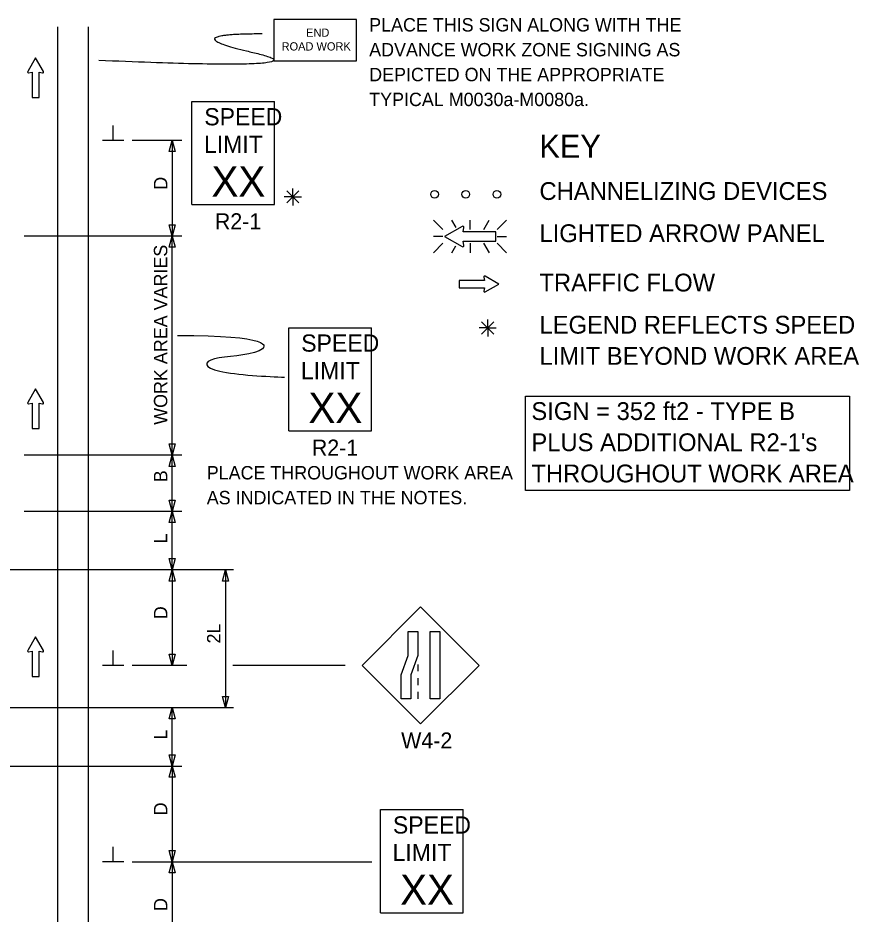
# Model space of a CAD drawing. Extents: x 16504 to 18480, y 5523 to 6928.
# Drawn here: x 16983.9 to 17424, y 6455.4 to 6923.9 of the extents above; entities that cross this region are included whole.
import ezdxf

# ---------------------------------------------------------------- set-up
doc = ezdxf.new("R2010")
doc.units = 0
for name, color, linetype in [('MT_SCRATCH_LEVEL_E', 7, 'Continuous'), ('PAVT_EDGE_EX', 7, 'Continuous'), ('TRAFFIC_SIGNS_PR', 7, 'Continuous'), ('TYPICAL_TEXT_DIMEN_EX', 7, 'Continuous'), ('TYPICAL_TEXT_DIMEN_PR', 7, 'Continuous')]:
    doc.layers.add(name, color=color, linetype=linetype)

msp = doc.modelspace()

# ---------------------------------------------------------------- linework, layer by layer
at = {"layer": 'MT_SCRATCH_LEVEL_E'}
for p, q in [((16993.16, 6903.1), (16989.05, 6895.86)), ((16997.31, 6895.86), (16993.16, 6903.1)), ((16989.53, 6895.17), (16991.31, 6895.49)), ((16991.31, 6895.49), (16991.31, 6882.23)), ((16995.05, 6882.23), (16995.05, 6895.49)), ((16995.05, 6895.49), (16996.83, 6895.17)), ((16991.31, 6882.23), (16995.05, 6882.23)), ((17227.93, 6786.61), (17214.67, 6786.61)), ((17214.67, 6786.61), (17214.67, 6782.86)), ((17227.62, 6788.38), (17227.93, 6786.61)), ((17235.54, 6784.76), (17228.3, 6788.87)), ((17228.3, 6780.61), (17235.54, 6784.76)), ((17214.67, 6782.86), (17227.93, 6782.86)), ((17227.93, 6782.86), (17227.62, 6781.09)), ((16993.16, 6730.05), (16989.05, 6722.81)), ((16997.31, 6722.81), (16993.16, 6730.05)), ((16989.53, 6722.12), (16991.31, 6722.44)), ((16991.31, 6722.44), (16991.31, 6709.18)), ((16995.05, 6709.18), (16995.05, 6722.44)), ((16995.05, 6722.44), (16996.83, 6722.12)), ((16991.31, 6709.18), (16995.05, 6709.18)), ((16993.16, 6600.4), (16989.05, 6593.16)), ((16997.31, 6593.16), (16993.16, 6600.4)), ((16989.53, 6592.48), (16991.31, 6592.79)), ((16991.31, 6592.79), (16991.31, 6579.54)), ((16995.05, 6579.54), (16995.05, 6592.79)), ((16995.05, 6592.79), (16996.83, 6592.48)), ((16991.31, 6579.54), (16995.05, 6579.54))]:
    msp.add_line(p, q, dxfattribs=at)
for centre, start, end in [((16989.46, 6895.63), 150.4248, 279.9638), ((16996.9, 6895.63), 260.0362, 29.7731), ((17228.07, 6788.46), 60.4248, 189.9638), ((17228.07, 6781.02), 170.0362, 299.7731), ((16989.46, 6722.58), 150.4248, 279.9638), ((16996.9, 6722.58), 260.0362, 29.7731), ((16989.46, 6592.94), 150.4248, 279.9638), ((16996.9, 6592.94), 260.0362, 29.7731)]:
    msp.add_arc(centre, 0.463, start, end, dxfattribs=at)
at = {"layer": 'PAVT_EDGE_EX'}
for p, q in [((17004.63, 6919.19), (17004.63, 6002.83)), ((17020.63, 6919.19), (17020.63, 6002.83))]:
    msp.add_line(p, q, dxfattribs=at)
at = {"layer": 'TRAFFIC_SIGNS_PR'}
for p, q in [((17074.95, 6880.28), (17118.15, 6880.28)), ((17074.95, 6826.28), (17074.95, 6880.28)), ((17118.15, 6826.28), (17118.15, 6880.28)), ((17074.95, 6826.28), (17118.15, 6826.28)), ((17201.35, 6818.14), (17206.28, 6813.21)), ((17213.11, 6814.32), (17210.91, 6818.14)), ((17220.43, 6813.21), (17220.43, 6818.14)), ((17227.67, 6813.21), (17230.52, 6818.14)), ((17234.58, 6813.21), (17239.52, 6818.14)), ((17206.28, 6809.65), (17201.35, 6809.65)), ((17234.58, 6809.65), (17239.52, 6809.65)), ((17201.35, 6801.16), (17206.28, 6806.09)), ((17210.86, 6801.16), (17212.97, 6804.82)), ((17220.43, 6806.09), (17220.43, 6801.16)), ((17230.56, 6801.16), (17227.71, 6806.09)), ((17234.58, 6806.09), (17239.52, 6801.16)), ((17125.67, 6761.94), (17168.87, 6761.94)), ((17125.67, 6707.94), (17125.67, 6761.94)), ((17168.87, 6707.94), (17168.87, 6761.94)), ((17125.67, 6707.94), (17168.87, 6707.94)), ((17194.59, 6615.92), (17164.04, 6585.37)), ((17225.13, 6585.37), (17194.59, 6615.92)), ((17164.04, 6585.37), (17194.59, 6554.82)), ((17193.18, 6585.92), (17193.18, 6582.32)), ((17194.59, 6554.82), (17225.13, 6585.37)), ((17193.18, 6578.72), (17193.18, 6575.12)), ((17193.18, 6571.52), (17193.18, 6567.92)), ((17173.61, 6510.02), (17216.81, 6510.02)), ((17173.61, 6456.02), (17173.61, 6510.02)), ((17216.81, 6456.02), (17216.81, 6510.02)), ((17173.61, 6456.02), (17216.81, 6456.02))]:
    msp.add_line(p, q, dxfattribs=at)
for points in [[(17117.81, 6901.54), (17161.01, 6901.54), (17161.01, 6923.14), (17117.81, 6923.14)], [(17193.18, 6603.07), (17193.18, 6590.49), (17189.42, 6580.5), (17189.42, 6567.92), (17184.37, 6567.92), (17184.37, 6580.5), (17188.13, 6590.49), (17188.13, 6603.07)], [(17204.59, 6603.07), (17204.59, 6567.92), (17199.53, 6567.92), (17199.53, 6603.07)]]:
    msp.add_lwpolyline(points, close=True, dxfattribs=at)
for points in [[(17216.36, 6814.93), (17207.07, 6809.65), (17216.36, 6804.33)], [(17217.24, 6804.96), (17216.83, 6807.22), (17233.85, 6807.22), (17233.85, 6812.03), (17216.83, 6812.03), (17217.24, 6814.31)]]:
    msp.add_lwpolyline(points, dxfattribs=at)
for centre in [(17201.91, 6831.68), (17218.21, 6831.68), (17234.51, 6831.68)]:
    msp.add_circle(centre, 2, dxfattribs=at)
for centre, radius, start, end in [((17216.65, 6814.4), 0.598, 350.7308, 118.8916), ((17216.65, 6804.85), 0.597, 241.4833, 9.9593)]:
    msp.add_arc(centre, radius, start, end, dxfattribs=at)
msp.add_open_spline([(17111.64, 6915.52), (17064.41, 6915.52), (17149.43, 6896.18), (17026.33, 6901.67)], degree=2, dxfattribs=at)
at = {"layer": 'TYPICAL_TEXT_DIMEN_EX'}
msp.add_lwpolyline([(17249.52, 6726.09), (17418.98, 6726.09), (17418.98, 6676.9), (17249.52, 6676.9)], close=True, dxfattribs=at)
at = {"layer": 'TYPICAL_TEXT_DIMEN_PR'}
for p, q in [((17033.76, 6859.85), (17033.76, 6867.64)), ((17039.38, 6859.85), (17028.13, 6859.85)), ((17069.63, 6859.85), (17043.63, 6859.85)), ((17063.06, 6853.99), (17064.63, 6859.85)), ((17064.63, 6859.85), (17064.63, 6809.85)), ((17064.63, 6859.85), (17066.2, 6853.99)), ((17064.63, 6853.99), (17063.06, 6853.99)), ((17066.2, 6853.99), (17064.63, 6853.99)), ((17124.58, 6833.53), (17130.95, 6827.15)), ((17130.95, 6833.53), (17124.58, 6827.15)), ((17127.76, 6830.34), (17127.76, 6834.8)), ((17127.76, 6830.34), (17123.23, 6830.34)), ((17127.76, 6830.34), (17130.95, 6830.34)), ((17127.76, 6830.34), (17132.24, 6830.34)), ((17127.76, 6830.34), (17127.76, 6825.84)), ((17064.63, 6809.85), (17063.06, 6815.71)), ((17063.06, 6815.71), (17064.63, 6815.71)), ((17064.63, 6815.71), (17066.2, 6815.71)), ((17066.2, 6815.71), (17064.63, 6809.85)), ((17069.63, 6809.85), (16987.24, 6809.85)), ((17063.06, 6803.99), (17064.63, 6809.85)), ((17064.63, 6695.32), (17064.63, 6809.85)), ((17064.63, 6809.85), (17066.2, 6803.99)), ((17064.63, 6803.99), (17063.06, 6803.99)), ((17066.2, 6803.99), (17064.63, 6803.99)), ((17229.69, 6761.81), (17229.69, 6766.26)), ((17229.69, 6761.81), (17225.16, 6761.81)), ((17226.5, 6764.99), (17232.88, 6758.62)), ((17232.88, 6764.99), (17226.5, 6758.62)), ((17229.69, 6761.81), (17232.88, 6761.81)), ((17229.69, 6761.81), (17234.17, 6761.81)), ((17229.69, 6761.81), (17229.69, 6757.31)), ((17064.63, 6695.32), (17063.06, 6701.18)), ((17063.06, 6701.18), (17064.63, 6701.18)), ((17064.63, 6701.18), (17066.2, 6701.18)), ((17066.2, 6701.18), (17064.63, 6695.32)), ((17069.63, 6695.32), (16987.24, 6695.32)), ((17063.06, 6689.45), (17064.63, 6695.32)), ((17064.63, 6665.89), (17064.63, 6695.32)), ((17064.63, 6695.32), (17066.2, 6689.45)), ((17064.63, 6689.45), (17063.06, 6689.45)), ((17066.2, 6689.45), (17064.63, 6689.45)), ((17064.63, 6665.89), (17063.06, 6671.75)), ((17063.06, 6671.75), (17064.63, 6671.75)), ((17064.63, 6671.75), (17066.2, 6671.75)), ((17066.2, 6671.75), (17064.63, 6665.89)), ((17069.63, 6665.89), (16987.24, 6665.89)), ((17063.06, 6660.03), (17064.63, 6665.89)), ((17064.63, 6635.32), (17064.63, 6665.89)), ((17064.63, 6665.89), (17066.2, 6660.03)), ((17064.63, 6660.03), (17063.06, 6660.03)), ((17066.2, 6660.03), (17064.63, 6660.03)), ((17064.63, 6635.32), (17063.06, 6641.19)), ((17063.06, 6641.19), (17064.63, 6641.19)), ((17064.63, 6641.19), (17066.2, 6641.19)), ((17066.2, 6641.19), (17064.63, 6635.32)), ((17096.68, 6635.32), (16965.53, 6635.32)), ((17063.06, 6629.46), (17064.63, 6635.32)), ((17064.63, 6635.32), (17064.63, 6585.32)), ((17064.63, 6635.32), (17066.2, 6629.46)), ((17090.87, 6629.46), (17092.44, 6635.32)), ((17092.44, 6635.32), (17094.01, 6629.46)), ((17092.44, 6635.32), (17092.44, 6563.32)), ((17064.63, 6629.46), (17063.06, 6629.46)), ((17066.2, 6629.46), (17064.63, 6629.46)), ((17092.44, 6629.46), (17090.87, 6629.46)), ((17094.01, 6629.46), (17092.44, 6629.46)), ((17033.76, 6585.32), (17033.76, 6593.11)), ((17064.63, 6585.32), (17063.06, 6591.19)), ((17063.06, 6591.19), (17064.63, 6591.19)), ((17064.63, 6591.19), (17066.2, 6591.19)), ((17066.2, 6591.19), (17064.63, 6585.32)), ((17092.44, 6590.19), (17092.44, 6586.43)), ((17039.38, 6585.32), (17028.13, 6585.32)), ((17072.33, 6585.32), (17043.63, 6585.32)), ((17155.06, 6585.32), (17096.37, 6585.32)), ((17092.44, 6563.32), (17090.87, 6569.19)), ((17090.87, 6569.19), (17092.44, 6569.19)), ((17092.44, 6569.19), (17094.01, 6569.19)), ((17094.01, 6569.19), (17092.44, 6563.32)), ((16965.53, 6563.32), (17096.68, 6563.32)), ((17063.06, 6557.46), (17064.63, 6563.32)), ((17064.63, 6532.76), (17064.63, 6563.32)), ((17064.63, 6563.32), (17066.2, 6557.46)), ((17064.63, 6557.46), (17063.06, 6557.46)), ((17066.2, 6557.46), (17064.63, 6557.46)), ((17064.63, 6532.76), (17063.06, 6538.62)), ((17063.06, 6538.62), (17064.63, 6538.62)), ((17064.63, 6538.62), (17066.2, 6538.62)), ((17066.2, 6538.62), (17064.63, 6532.76)), ((16941.8, 6532.76), (17069.63, 6532.76)), ((17063.06, 6526.9), (17064.63, 6532.76)), ((17064.63, 6532.76), (17064.63, 6482.76)), ((17064.63, 6532.76), (17066.2, 6526.9)), ((17064.63, 6526.9), (17063.06, 6526.9)), ((17066.2, 6526.9), (17064.63, 6526.9)), ((17033.76, 6482.76), (17033.76, 6490.55)), ((17064.63, 6482.76), (17063.06, 6488.62)), ((17063.06, 6488.62), (17064.63, 6488.62)), ((17064.63, 6488.62), (17066.2, 6488.62)), ((17066.2, 6488.62), (17064.63, 6482.76)), ((17039.38, 6482.76), (17028.13, 6482.76)), ((17043.63, 6482.76), (17169.12, 6482.76)), ((17063.06, 6476.9), (17064.63, 6482.76)), ((17064.63, 6482.76), (17064.63, 6432.76)), ((17064.63, 6482.76), (17066.2, 6476.9)), ((17064.63, 6476.9), (17063.06, 6476.9)), ((17066.2, 6476.9), (17064.63, 6476.9))]:
    msp.add_line(p, q, dxfattribs=at)
for points, degree in [([(17288.16, 6804.54), (17288.17, 6804.54), (17288.18, 6804.54), (17288.18, 6804.54)], 2), ([(17067.4, 6757.92), (17115.87, 6757.92), (17115.87, 6747.17), (17080.95, 6747.17), (17080.95, 6738.12), (17115.15, 6736.36), (17123.45, 6736.07)], 3)]:
    msp.add_open_spline(points, degree=degree, dxfattribs=at)

# ---------------------------------------------------------------- texts
at = {"layer": 'TRAFFIC_SIGNS_PR'}
for s, height, p in [('PLACE THIS SIGN ALONG WITH THE', 7, (17167.68, 6916.8)), ('END', 4.31, (17134.69, 6914.06)), ('ROAD WORK', 4.31, (17121.87, 6906.87)), ('ADVANCE WORK ZONE SIGNING AS', 7, (17167.68, 6903.8)), ('DEPICTED ON THE APPROPRIATE', 7, (17167.68, 6890.8)), ('TYPICAL M0030a-M0080a.', 7, (17167.68, 6877.8)), ('SPEED', 9, (17081.44, 6867.74)), ('LIMIT', 9, (17081.26, 6853.34)), ('XX', 15.785, (17085.2, 6830.5)), ('R2-1', 8.37, (17086.96, 6813.4)), ('SPEED', 9, (17132.15, 6749.41)), ('LIMIT', 9, (17131.97, 6735.01)), ('XX', 15.785, (17135.92, 6712.17)), ('R2-1', 8.37, (17137.68, 6695.07)), ('PLACE THROUGHOUT WORK AREA', 7, (17082.72, 6682.61)), ('AS INDICATED IN THE NOTES.', 7, (17082.72, 6669.61)), ('W4-2', 8.37, (17184.41, 6541.95)), ('SPEED', 9, (17180.1, 6497.48)), ('LIMIT', 9, (17179.92, 6483.08)), ('XX', 15.785, (17183.86, 6460.24))]:
    msp.add_text(s, height=height, dxfattribs=at).set_placement(p)
at = {"layer": 'TYPICAL_TEXT_DIMEN_EX'}
for s, height, p in [('KEY', 12, (17256.75, 6850.79)), ('CHANNELIZING DEVICES', 9.3, (17256.75, 6828.74)), ('LIGHTED ARROW PANEL', 9.3, (17256.75, 6806.69)), ('TRAFFIC FLOW', 9.3, (17256.75, 6780.89)), ('LEGEND REFLECTS SPEED', 9.3, (17256.75, 6758.84)), ('LIMIT BEYOND WORK AREA', 9.3, (17256.75, 6742.54)), ('SIGN = 352 ft2 - TYPE B', 9.3, (17252.53, 6713.69)), ("PLUS ADDITIONAL R2-1's", 9.3, (17252.53, 6697.39)), ('THROUGHOUT WORK AREA', 9.3, (17252.53, 6681.09))]:
    msp.add_text(s, height=height, dxfattribs=at).set_placement(p)
at = {"layer": 'TYPICAL_TEXT_DIMEN_PR'}
for s, p in [('D', (17062.08, 6834.07)), ('WORK AREA VARIES', (17062.08, 6711.17)), ('B', (17062.08, 6681.15)), ('L', (17062.08, 6649.18)), ('D', (17062.08, 6609.54)), ('2L', (17089.88, 6596.83)), ('L', (17062.08, 6546.62)), ('D', (17062.08, 6506.98)), ('D', (17062.08, 6456.98))]:
    msp.add_text(s, height=7, rotation=90, dxfattribs=at).set_placement(p)

doc.saveas('drawing.dxf')
